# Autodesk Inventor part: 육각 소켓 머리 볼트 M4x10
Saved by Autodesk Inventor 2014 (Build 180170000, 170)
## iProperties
Created: 2024-05
Part Number: 육각 소켓 머리 볼트 M4x10
Material: 일반
Document SubType Name: Modeling
Designer: dg
Density: 1 g/cm^3
Appearance: 기본값
Author: dg
Author: jhkim
Description: 6각머리 태핑 나사
Creation Date: 2024-05-07
Sending System: Autodesk Inventor 2025
Preprocessor: ST-DEVELOPER v20
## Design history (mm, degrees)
node "육각 소켓 머리 볼트 M4x101"
body "Solid1"
node "기준1"
